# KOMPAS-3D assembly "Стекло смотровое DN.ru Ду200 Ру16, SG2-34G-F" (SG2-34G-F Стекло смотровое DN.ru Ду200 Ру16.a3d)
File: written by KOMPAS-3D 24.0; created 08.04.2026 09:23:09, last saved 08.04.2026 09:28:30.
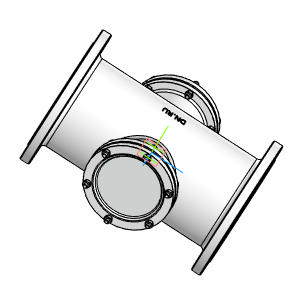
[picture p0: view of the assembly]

Document properties: Автор: Main; Полное имя файла: D:\DN.ru Аутсерс\Стекло смотровое DN.ru\Исходники\Стекло смотровое DN.ru SG2-34G-F тип В ГОСТ 21836-2021 Ду200 Ру16, углеродистая сталь, фланцевое\SG2-34G-F Стекло смотровое DN.ru Ду200 Ру16.a3d

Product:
- Component [detail]: Деталь  | qty 1  | pos. 1  | Масса: 62.247017; Автор: Main; additional columns: Типовые; source file: ДетальДеталь.m3d
- Component [detail]: Стекло  | qty 2  | pos. 2  | Масса: 1.895451; Автор: Main; source file: СтеклоСтекло.m3d
- Component [detail]: ANSI B18.2.4.2M - M10x1,5 - 16  | designation ANSI B18.2.4.2M - M10x1,5  | qty 24  | pos. 3  | Масса: 0.012122; Комментарий: Типы метрических   шестигранных гаек   2; Автор: Main; additional columns: Сталь, мягкая; source file: ANSI B18.2.4.2M - M10x1,5ANSI B18.2.4.2M - M10x1,5 - 16.m3d
- Part/product: Стекло смотровое DN.ru Ду200 Ру16  | designation SG2-34G-F
    Масса: 55
    Раздел спецификации: Прочие изделия
    Примечание: D500-00090

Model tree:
1. Массив по концентрической сетке:1  (labels: Грань.Твердое тело1; Грань.Solid1; Ребро.Твердое тело1; Ребро.Solid1)  (6 pattern instances)
     Шаг 2 = 360

Expressions: SG2-34G-F
Referenced files in D:\DN.ru Аутсерс\Стекло смотровое DN.ru\Исходники\Стекло смотровое DN.ru SG2-34G-F тип В ГОСТ 21836-2021 Ду200 Ру16, углеродистая сталь, фланцевое\: ДетальДеталь.m3d, СтеклоСтекло.m3d, ANSI B18.2.4.2M - M10x1,5ANSI B18.2.4.2M - M10x1,5 - 16.m3d
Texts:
  Стекло Стекло (1)
  Стекло Стекло (2)
  ANSI B18.2.4.2M - M10x1,5 ANSI B18.2.4.2M - M10x1,5 - 16 (1)
  ANSI B18.2.4.2M - M10x1,5 ANSI B18.2.4.2M - M10x1,5 - 16 (2)
  ANSI B18.2.4.2M - M10x1,5 ANSI B18.2.4.2M - M10x1,5 - 16 (3)
  ANSI B18.2.4.2M - M10x1,5 ANSI B18.2.4.2M - M10x1,5 - 16 (4)
  ANSI B18.2.4.2M - M10x1,5 ANSI B18.2.4.2M - M10x1,5 - 16 (5)
  ANSI B18.2.4.2M - M10x1,5 ANSI B18.2.4.2M - M10x1,5 - 16 (6)
  ANSI B18.2.4.2M - M10x1,5 ANSI B18.2.4.2M - M10x1,5 - 16 (7)
  ANSI B18.2.4.2M - M10x1,5 ANSI B18.2.4.2M - M10x1,5 - 16 (8)
  ANSI B18.2.4.2M - M10x1,5 ANSI B18.2.4.2M - M10x1,5 - 16 (9)
  ANSI B18.2.4.2M - M10x1,5 ANSI B18.2.4.2M - M10x1,5 - 16 (10)
  ANSI B18.2.4.2M - M10x1,5 ANSI B18.2.4.2M - M10x1,5 - 16 (11)
  ANSI B18.2.4.2M - M10x1,5 ANSI B18.2.4.2M - M10x1,5 - 16 (12)
  ANSI B18.2.4.2M - M10x1,5 ANSI B18.2.4.2M - M10x1,5 - 16 (13)
  ANSI B18.2.4.2M - M10x1,5 ANSI B18.2.4.2M - M10x1,5 - 16 (14)
  ANSI B18.2.4.2M - M10x1,5 ANSI B18.2.4.2M - M10x1,5 - 16 (15)
  ANSI B18.2.4.2M - M10x1,5 ANSI B18.2.4.2M - M10x1,5 - 16 (16)
  ANSI B18.2.4.2M - M10x1,5 ANSI B18.2.4.2M - M10x1,5 - 16 (17)
  ANSI B18.2.4.2M - M10x1,5 ANSI B18.2.4.2M - M10x1,5 - 16 (18)
  ANSI B18.2.4.2M - M10x1,5 ANSI B18.2.4.2M - M10x1,5 - 16 (19)
  ANSI B18.2.4.2M - M10x1,5 ANSI B18.2.4.2M - M10x1,5 - 16 (20)
  ANSI B18.2.4.2M - M10x1,5 ANSI B18.2.4.2M - M10x1,5 - 16 (21)
  ANSI B18.2.4.2M - M10x1,5 ANSI B18.2.4.2M - M10x1,5 - 16 (22)
  ANSI B18.2.4.2M - M10x1,5 ANSI B18.2.4.2M - M10x1,5 - 16 (23)
  ANSI B18.2.4.2M - M10x1,5 ANSI B18.2.4.2M - M10x1,5 - 16 (24)
  Ось Z.Начало координат
  Ось X.Начало координат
